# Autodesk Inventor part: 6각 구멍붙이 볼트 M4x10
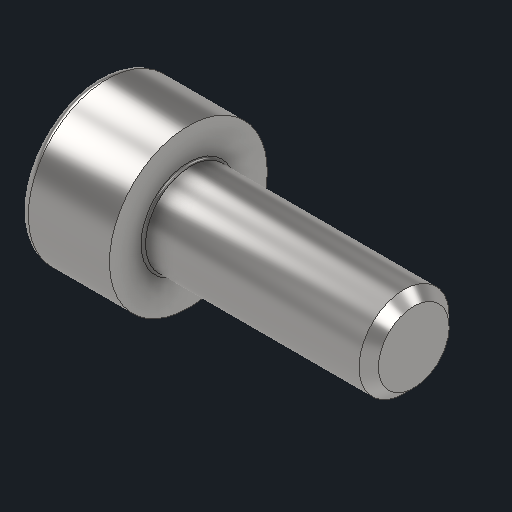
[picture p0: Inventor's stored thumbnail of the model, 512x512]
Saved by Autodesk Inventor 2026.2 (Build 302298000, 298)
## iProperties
Created: 2025-11
Part Number: 6각 구멍붙이 볼트 M4x10
Material: 강철, 연강
Description: 6각머리 태핑 나사
Document SubType Name: Modeling
Designer: PC2-07
Density: 7.85 g/cm^3
Appearance: 기본값
Author: jhkim
Sending System: Autodesk Inventor 2026
Preprocessor: ST-DEVELOPER v20.1
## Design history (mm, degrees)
feature "Solid1"
node "솔리드1"
